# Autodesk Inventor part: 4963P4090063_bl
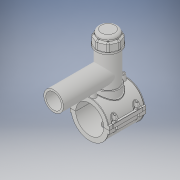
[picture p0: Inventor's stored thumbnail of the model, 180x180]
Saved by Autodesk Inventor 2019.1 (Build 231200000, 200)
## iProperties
Created: 2017-07
Part Number: 4963P4090063_bl
Material: Generic
Document SubType Name: Modeling
Designer: KIM
Density: 1 g/cm^3
Appearance: Default
Author: KIM
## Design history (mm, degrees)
derived "4963P4.ipt"
feature "Solid1::4963P4.ipt" dims "ScaleForDerivedMember" = 10
feature "Solid2::4963P4.ipt" dims "ScaleForDerivedMember" = 10
feature "Solid3::4963P4.ipt" dims "ScaleForDerivedMember" = 10
tag "TaggingFeature1"
body "Solid1"
body "Solid2"
body "Solid3"
other parameters: "d2" = 126 [user parameter], "d3" = 22.5 [user parameter], "d4" = 118 [user parameter], "d5" = 0 [user parameter], "d6" = 0.1 [user parameter], "d8" = 0 [user parameter], "d19" = 6 [user parameter], "d20" = 6 [user parameter], "d21" = 70.8 [user parameter], "d23" = 0 [user parameter], "d24" = 35.4 [user parameter], "d26" = 0 [user parameter], "d27" = 3 [user parameter], "d28" = 3 [user parameter], "d29" = 3 [user parameter], "d31" = 6 [user parameter], "d32" = 0 [user parameter], "d33" = 0 [user parameter], "d34" = 0.6 [user parameter], "d40" = 60.84 [user parameter], "d41" = 76.5 [user parameter], "d43" = 0 [user parameter], "d45" = 0 [user parameter], "d47" = 129.3 [user parameter], "d70" = 15 [user parameter], "d72" = 0 [user parameter], "d73" = 6 [user parameter], "d75" = 5 [user parameter], "d76" = 0 [user parameter], "d77" = 4.5 [user parameter], "d78" = 75 [user parameter], "d79" = 15 [user parameter], "d80" = 47.2 [user parameter], "d82" = 5 deg [user parameter], "d84" = 4 [user parameter], "d85" = 14 [user parameter], "d86" = 0 [user parameter], "d87" = 3 [user parameter], "d88" = 0 [user parameter], "d89" = 1 [user parameter], "d90" = 1 [user parameter], "d91" = 94.4 [user parameter], "d92" = 0 [user parameter], "d93" = 0.5 [user parameter], "d94" = 47.36842 [user parameter], "d96" = 119.34 [user parameter], "d97" = 2.36 [user parameter], "d98" = 0 [user parameter], "d102" = 0.9 [user parameter], "d120" = 140 deg [user parameter], "d121" = 24.228 [user parameter], "d122" = 20 deg [user parameter], "d123" = 234 [user parameter], "d124" = 70.2 [user parameter], "d126" = 0 [user parameter], "d143" = 92.7 [user parameter], "d145" = 20.76923 [user parameter], "d149" = 1.35 [user parameter], "d150" = 22.84615 [user parameter], "d153" = 118 [user parameter], "d154" = 0 [user parameter], "d156" = 58.5 [user parameter], "d157" = 160 deg [user parameter], "d159" = 5.4 [user parameter], "d161" = 1.35 [user parameter], "d162" = 70.8 [user parameter], "d163" = 0 [user parameter], "d164" = 45 [user parameter], "d167" = 9 [user parameter], "d168" = 57.07317 [user parameter], "d170" = 3.75 [user parameter], "d172" = 0 [user parameter], "d173" = 1 [user parameter], "d175" = 45 [user parameter], "d176" = 20 deg [user parameter], "d177" = 6.3 [user parameter], "d178" = 27 [user parameter], "d180" = 0 [user parameter], "d183" = 10.8 [user parameter], "d184" = 5.04 [user parameter], "d185" = 38.35 [user parameter], "d186" = 38.35 [user parameter], "d187" = 58.5 [user parameter], "d188" = 8.1 [user parameter], "d189" = 6.3 [user parameter], "d190" = 0 [user parameter], "d191" = 87.75 [user parameter], "d193" = 8 [user parameter], "d194" = 4.13 [user parameter], "d195" = 90 deg [user parameter], "d197" = 0 [user parameter], "d199" = 0 [user parameter], "d200" = 13.5 [user parameter], "d202" = 0 [user parameter], "d203" = 177 [user parameter], "d204" = 72.675 [user parameter], "d205" = 53.55 [user parameter], "d206" = 65.025 [user parameter], "d207" = 132.75 [user parameter], "d208" = 138.06 [user parameter], "d209" = 164.61 [user parameter], "d210" = 65.79 [user parameter], "d211" = 76.5 [user parameter], "d212" = 61.2 [user parameter], "d213" = 29.25 [user parameter], "d216" = 0 [user parameter], "d217" = 9 [user parameter], "d218" = 9 [user parameter], "d219" = 1.8 [user parameter], "d224" = 0 [user parameter], "d225" = 64 [user parameter], "d226" = 63 [user parameter], "d227" = 50.4 [user parameter], "d228" = 175 [user parameter], "d230" = 5.4 [user parameter], "B_" = 126 [user parameter], "L_" = 118 [user parameter], "d_t" = 6 [user parameter], "H_2" = 177 [user parameter], "H_1" = 64 [user parameter]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
